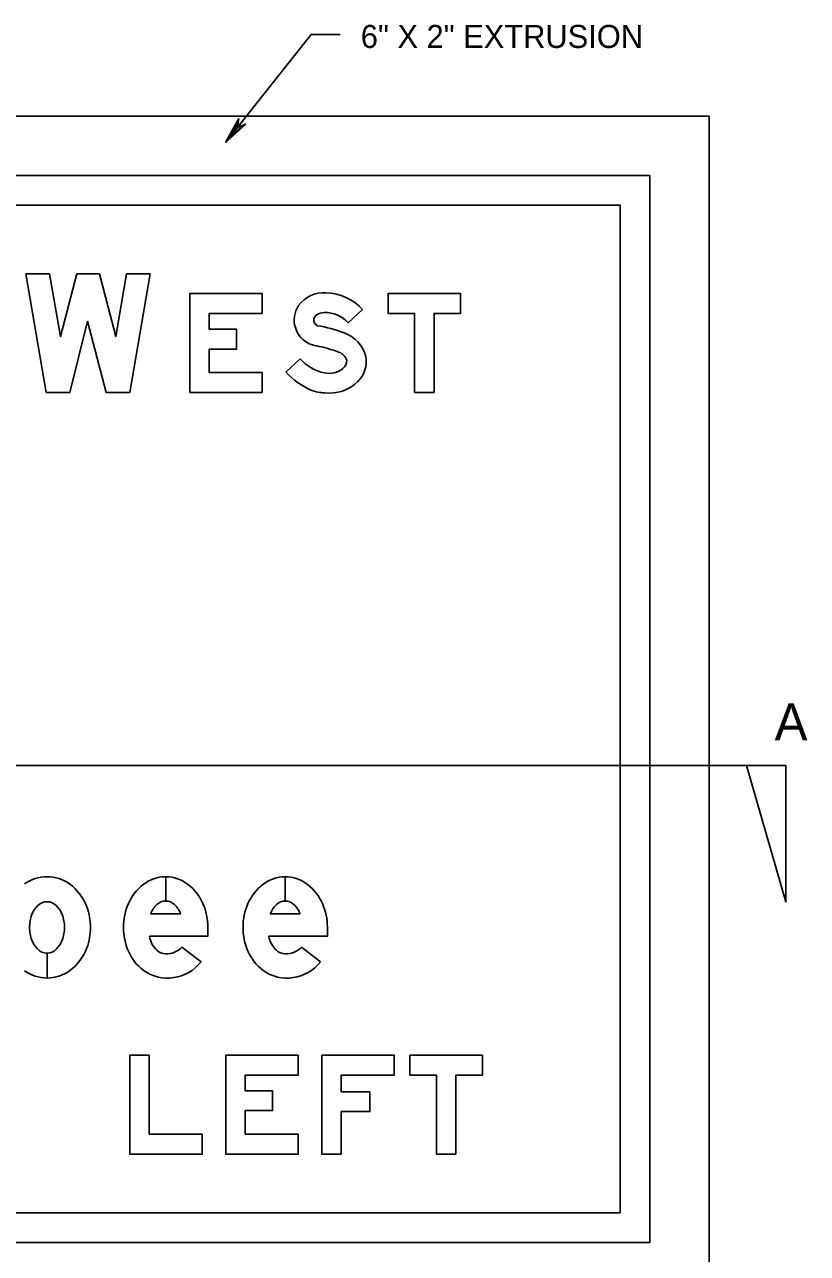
# Model space of a CAD drawing. Extents: x -897 to -114, y -697 to -235.
# Drawn here: x -281.9 to -163, y -536.1 to -349.4 of the extents above; entities that cross this region are included whole.
import ezdxf

# ---------------------------------------------------------------- set-up
doc = ezdxf.new("R2010")
doc.units = 0
for name, color, linetype in [('52', 7, 'Continuous'), ('SignPanel', 7, 'Continuous'), ('TextLabel', 7, 'Continuous')]:
    doc.layers.add(name, color=color, linetype=linetype)

msp = doc.modelspace()

# ---------------------------------------------------------------- linework, layer by layer
at = {"layer": '52'}
msp.add_lwpolyline([(-401.43, -482.68), (-401.43, -461.97), (-166.27, -461.97), (-166.27, -482.68)], dxfattribs=at)
msp.add_lwpolyline([(-166.27, -461.97), (-172.27, -461.97), (-166.27, -482.68)], close=True, dxfattribs=at)
at = {"layer": 'SignPanel'}
for p, q in [((-232.75, -394.74), (-230.57, -392.71)), ((-232.75, -394.74), (-230.57, -392.71)), ((-232.75, -394.74), (-230.57, -392.71)), ((-240.03, -400.18), (-242.22, -402.2)), ((-240.03, -400.18), (-242.22, -402.2)), ((-240.03, -400.18), (-242.22, -402.2)), ((-260.45, -478.84), (-260.45, -482.54)), ((-260.45, -482.54), (-260.45, -478.84)), ((-260.45, -478.84), (-260.45, -482.54)), ((-260.45, -482.54), (-260.45, -478.84)), ((-242.3, -478.84), (-242.3, -482.54)), ((-242.3, -482.54), (-242.3, -478.84)), ((-242.3, -478.84), (-242.3, -482.54)), ((-242.3, -482.54), (-242.3, -478.84)), ((-262.73, -484.47), (-258.17, -484.47)), ((-262.73, -484.47), (-258.17, -484.47)), ((-262.73, -484.47), (-258.17, -484.47)), ((-244.58, -484.47), (-240.02, -484.47)), ((-244.58, -484.47), (-240.02, -484.47)), ((-244.58, -484.47), (-240.02, -484.47)), ((-278.46, -490.44), (-278.46, -494.24)), ((-278.46, -494.24), (-278.46, -490.44)), ((-278.46, -490.44), (-278.46, -494.24)), ((-278.46, -494.24), (-278.46, -490.44)), ((-257.99, -489.52), (-255.08, -491.76)), ((-257.99, -489.52), (-255.08, -491.76)), ((-257.99, -489.52), (-255.08, -491.76)), ((-239.84, -489.52), (-236.93, -491.76)), ((-239.84, -489.52), (-236.93, -491.76)), ((-239.84, -489.52), (-236.93, -491.76))]:
    msp.add_line(p, q, dxfattribs=at)
for points in [[(-384.93, -543.37), (-177.93, -543.37), (-177.93, -363.37), (-384.93, -363.37)], [(-375.93, -534.37), (-186.93, -534.37), (-186.93, -372.37), (-375.93, -372.37)], [(-375.93, -534.37), (-186.93, -534.37), (-186.93, -372.37), (-375.93, -372.37)], [(-371.43, -529.87), (-191.43, -529.87), (-191.43, -376.87), (-371.43, -376.87)], [(-371.43, -529.87), (-371.43, -376.87), (-191.43, -376.87), (-191.43, -529.87)], [(-278.58, -405.3), (-281.67, -387.3), (-278.07, -387.3), (-276.43, -396.83), (-273.94, -387.3), (-270.51, -387.3), (-268.02, -396.83), (-266.38, -387.3), (-262.78, -387.3), (-265.87, -405.3), (-269.47, -405.3), (-272.3, -394.5), (-274.98, -405.3)], [(-278.58, -405.3), (-281.67, -387.3), (-278.07, -387.3), (-276.43, -396.83), (-273.94, -387.3), (-270.51, -387.3), (-268.02, -396.83), (-266.38, -387.3), (-262.78, -387.3), (-265.87, -405.3), (-269.47, -405.3), (-272.3, -394.5), (-274.98, -405.3)], [(-278.58, -405.3), (-281.67, -387.3), (-278.07, -387.3), (-276.43, -396.83), (-273.94, -387.3), (-270.51, -387.3), (-268.02, -396.83), (-266.38, -387.3), (-262.78, -387.3), (-265.87, -405.3), (-269.47, -405.3), (-272.3, -394.5), (-274.98, -405.3)], [(-245.78, -390.3), (-245.78, -393.3), (-253.83, -393.3), (-253.83, -395.71), (-249.68, -395.71), (-249.68, -398.71), (-253.83, -398.71), (-253.83, -402.3), (-245.78, -402.3), (-245.78, -405.3), (-256.78, -405.3), (-256.78, -390.3)], [(-245.78, -390.3), (-245.78, -393.3), (-253.83, -393.3), (-253.83, -395.71), (-249.68, -395.71), (-249.68, -398.71), (-253.83, -398.71), (-253.83, -402.3), (-245.78, -402.3), (-245.78, -405.3), (-256.78, -405.3), (-256.78, -390.3)], [(-245.78, -390.3), (-245.78, -393.3), (-253.83, -393.3), (-253.83, -395.71), (-249.68, -395.71), (-249.68, -398.71), (-253.83, -398.71), (-253.83, -402.3), (-245.78, -402.3), (-245.78, -405.3), (-256.78, -405.3), (-256.78, -390.3)], [(-219.69, -405.3), (-222.65, -405.3), (-222.65, -393.3), (-226.67, -393.3), (-226.67, -390.3), (-215.67, -390.3), (-215.67, -393.3), (-219.69, -393.3)], [(-219.69, -405.3), (-222.65, -405.3), (-222.65, -393.3), (-226.67, -393.3), (-226.67, -390.3), (-215.67, -390.3), (-215.67, -393.3), (-219.69, -393.3)], [(-219.69, -405.3), (-222.65, -405.3), (-222.65, -393.3), (-226.67, -393.3), (-226.67, -390.3), (-215.67, -390.3), (-215.67, -393.3), (-219.69, -393.3)], [(-262.94, -517.96), (-254.89, -517.96), (-254.89, -520.96), (-265.9, -520.96), (-265.9, -505.96), (-262.94, -505.96)], [(-262.94, -517.96), (-254.89, -517.96), (-254.89, -520.96), (-265.9, -520.96), (-265.9, -505.96), (-262.94, -505.96)], [(-262.94, -517.96), (-254.89, -517.96), (-254.89, -520.96), (-265.9, -520.96), (-265.9, -505.96), (-262.94, -505.96)], [(-240.31, -505.96), (-240.31, -508.96), (-248.36, -508.96), (-248.36, -511.37), (-244.22, -511.37), (-244.22, -514.37), (-248.36, -514.37), (-248.36, -517.96), (-240.31, -517.96), (-240.31, -520.96), (-251.32, -520.96), (-251.32, -505.96)], [(-240.31, -505.96), (-240.31, -508.96), (-248.36, -508.96), (-248.36, -511.37), (-244.22, -511.37), (-244.22, -514.37), (-248.36, -514.37), (-248.36, -517.96), (-240.31, -517.96), (-240.31, -520.96), (-251.32, -520.96), (-251.32, -505.96)], [(-240.31, -505.96), (-240.31, -508.96), (-248.36, -508.96), (-248.36, -511.37), (-244.22, -511.37), (-244.22, -514.37), (-248.36, -514.37), (-248.36, -517.96), (-240.31, -517.96), (-240.31, -520.96), (-251.32, -520.96), (-251.32, -505.96)], [(-236.74, -505.96), (-225.74, -505.96), (-225.74, -508.96), (-233.79, -508.96), (-233.79, -511.52), (-229.43, -511.52), (-229.43, -514.52), (-233.79, -514.52), (-233.79, -520.96), (-236.74, -520.96)], [(-236.74, -505.96), (-225.74, -505.96), (-225.74, -508.96), (-233.79, -508.96), (-233.79, -511.52), (-229.43, -511.52), (-229.43, -514.52), (-233.79, -514.52), (-233.79, -520.96), (-236.74, -520.96)], [(-236.74, -505.96), (-225.74, -505.96), (-225.74, -508.96), (-233.79, -508.96), (-233.79, -511.52), (-229.43, -511.52), (-229.43, -514.52), (-233.79, -514.52), (-233.79, -520.96), (-236.74, -520.96)], [(-216.38, -520.96), (-219.33, -520.96), (-219.33, -508.96), (-223.36, -508.96), (-223.36, -505.96), (-212.35, -505.96), (-212.35, -508.96), (-216.38, -508.96)], [(-216.38, -520.96), (-219.33, -520.96), (-219.33, -508.96), (-223.36, -508.96), (-223.36, -505.96), (-212.35, -505.96), (-212.35, -508.96), (-216.38, -508.96)], [(-216.38, -520.96), (-219.33, -520.96), (-219.33, -508.96), (-223.36, -508.96), (-223.36, -505.96), (-212.35, -505.96), (-212.35, -508.96), (-216.38, -508.96)]]:
    msp.add_lwpolyline(points, close=True, dxfattribs=at)
for points in [[(-254.05, -486.54), (-254.05, -487.88), (-262.93, -487.88)], [(-254.05, -486.54), (-254.05, -487.88), (-262.93, -487.88)], [(-254.05, -486.54), (-254.05, -487.88), (-262.93, -487.88)], [(-235.9, -486.54), (-235.9, -487.88), (-244.78, -487.88)], [(-235.9, -486.54), (-235.9, -487.88), (-244.78, -487.88)], [(-235.9, -486.54), (-235.9, -487.88), (-244.78, -487.88)]]:
    msp.add_lwpolyline(points, dxfattribs=at)
for centre, major_axis, start_param, end_param in [((-236.38, -395.12), (0, 4.97), 6.22585, 7.204805), ((-236.38, -395.12), (0, 4.97), 6.22585, 7.204805), ((-236.38, -395.12), (0, 4.97), 6.22585, 7.204805), ((-236.32, -398.11), (0, 7.96), 5.45828, 6.253918), ((-236.32, -398.11), (0, 7.96), 5.45828, 6.253918), ((-236.32, -398.11), (0, 7.96), 5.45828, 6.253918), ((-237.07, -394.31), (0, 3.92), 0.976932, 2.761526), ((-237.07, -394.31), (0, 3.92), 0.976932, 2.761526), ((-237.07, -394.31), (0, 3.92), 0.976932, 2.761526), ((-237.09, -394.32), (0, 0.896), 0.489453, 2.797937), ((-237.09, -394.32), (0, 0.896), 0.489453, 2.797937), ((-237.09, -394.32), (0, 0.896), 0.489453, 2.797937), ((-236.27, -395.53), (0, 2.36), 0.051099, 0.560381), ((-236.27, -395.53), (0, 2.36), 0.051099, 0.560381), ((-236.27, -395.53), (0, 2.36), 0.051099, 0.560381), ((-236.15, -397.75), (0, 4.58), 5.429459, 6.3353), ((-236.15, -397.75), (0, 4.58), 5.429459, 6.3353), ((-236.15, -397.75), (0, 4.58), 5.429459, 6.3353), ((-241.01, -417.14), (0, 22.28), 5.927499, 6.117503), ((-241.01, -417.14), (0, 22.28), 5.927499, 6.117503), ((-241.01, -417.14), (0, 22.28), 5.927499, 6.117503), ((-234.96, -401.16), (0, 5.16), 4.967514, 5.964052), ((-234.96, -401.16), (0, 5.16), 4.967514, 5.964052), ((-234.96, -401.16), (0, 5.16), 4.967514, 5.964052), ((-235.56, -389.29), (0, 9.16), 2.808858, 2.963856), ((-235.56, -389.29), (0, 9.16), 2.808858, 2.963856), ((-235.56, -389.29), (0, 9.16), 2.808858, 2.963856), ((-242.79, -424.08), (0, 26.4), 5.940509, 6.064763), ((-242.79, -424.08), (0, 26.4), 5.940509, 6.064763), ((-242.79, -424.08), (0, 26.4), 5.940509, 6.064763), ((-234.8, -401.03), (0, 1.97), 5.035719, 5.886297), ((-234.8, -401.03), (0, 1.97), 5.035719, 5.886297), ((-234.8, -401.03), (0, 1.97), 5.035719, 5.886297), ((-235.05, -395.76), (0, 6.71), 2.289515, 2.944644), ((-235.05, -395.76), (0, 6.71), 2.289515, 2.944644), ((-235.05, -395.76), (0, 6.71), 2.289515, 2.944644), ((-234.47, -400.48), (0, 1.53), 3.808537, 4.760948), ((-234.47, -400.48), (0, 1.53), 3.808537, 4.760948), ((-234.47, -400.48), (0, 1.53), 3.808537, 4.760948), ((-234.18, -400.57), (0, 4.26), 3.912503, 4.881073), ((-234.18, -400.57), (0, 4.26), 3.912503, 4.881073), ((-234.18, -400.57), (0, 4.26), 3.912503, 4.881073), ((-233.55, -393.9), (0, 12.09), 2.326579, 2.726842), ((-233.55, -393.9), (0, 12.09), 2.326579, 2.726842), ((-233.55, -393.9), (0, 12.09), 2.326579, 2.726842), ((-235.66, -398.84), (0, 3.57), 2.944399, 3.788539), ((-235.66, -398.84), (0, 3.57), 2.944399, 3.788539), ((-235.66, -398.84), (0, 3.57), 2.944399, 3.788539), ((-235.58, -399.14), (0, 6.28), 3.01776, 3.916355), ((-235.58, -399.14), (0, 6.28), 3.01776, 3.916355), ((-235.58, -399.14), (0, 6.28), 3.01776, 3.916355), ((-235.86, -397.44), (0, 7.95), 2.817761, 3.079327), ((-235.86, -397.44), (0, 7.95), 2.817761, 3.079327), ((-235.86, -397.44), (0, 7.95), 2.817761, 3.079327), ((-278.46, -484.82), (0, 5.98), 0, 0.617483), ((-278.46, -484.82), (0, 5.98), 0, 0.617483), ((-278.46, -484.82), (0, 5.98), 0, 0.617483), ((-278.46, -484.82), (0, 5.98), 5.665702, 6.283185), ((-278.46, -484.82), (0, 5.98), 5.665702, 6.283185), ((-278.46, -484.82), (0, 5.98), 5.665702, 6.283185), ((-260.45, -484.5), (0, 5.66), 0, 0.658026), ((-260.45, -484.5), (0, 5.66), 0, 0.658026), ((-260.45, -484.5), (0, 5.66), 0, 0.658026), ((-260.45, -484.5), (0, 5.66), 5.625159, 6.283185), ((-260.45, -484.5), (0, 5.66), 5.62516, 6.283009), ((-260.45, -484.5), (0, 5.66), 5.62516, 6.283009), ((-242.3, -484.5), (0, 5.66), 0, 0.658026), ((-242.3, -484.5), (0, 5.66), 0, 0.658026), ((-242.3, -484.5), (0, 5.66), 0, 0.658026), ((-242.3, -484.5), (0, 5.66), 5.625159, 6.283185), ((-242.3, -484.5), (0, 5.66), 5.62516, 6.283009), ((-242.3, -484.5), (0, 5.66), 5.62516, 6.283009), ((-279.37, -486.06), (0, 7.52), 5.067913, 5.660802), ((-279.37, -486.06), (0, 7.52), 5.067913, 5.660802), ((-279.37, -486.06), (0, 7.52), 5.067913, 5.660802), ((-259.46, -485.87), (0, 7.36), 0.651793, 1.157519), ((-259.46, -485.87), (0, 7.36), 0.651793, 1.157519), ((-259.46, -485.87), (0, 7.36), 0.651793, 1.157519), ((-261.44, -485.87), (0, 7.36), 5.125666, 5.631392), ((-261.44, -485.87), (0, 7.36), 5.125666, 5.631392), ((-261.44, -485.87), (0, 7.36), 5.125666, 5.631392), ((-241.31, -485.87), (0, 7.36), 0.651793, 1.157519), ((-241.31, -485.87), (0, 7.36), 0.651793, 1.157519), ((-241.31, -485.87), (0, 7.36), 0.651793, 1.157519), ((-243.29, -485.87), (0, 7.36), 5.125666, 5.631392), ((-243.29, -485.87), (0, 7.36), 5.125666, 5.631392), ((-243.29, -485.87), (0, 7.36), 5.125666, 5.631392), ((-277.3, -485.96), (0, 3.77), 0.7749, 1.203152), ((-277.3, -485.96), (0, 3.77), 0.7749, 1.203152), ((-277.3, -485.96), (0, 3.77), 0.7749, 1.203152), ((-278.46, -484.67), (0, 2.03), 0, 0.804581), ((-278.46, -484.67), (0, 2.03), 0, 0.804581), ((-278.46, -484.67), (0, 2.03), 0, 0.804581), ((-278.46, -484.67), (0, 2.03), 5.478604, 6.283185), ((-278.46, -484.67), (0, 2.03), 5.478604, 6.283185), ((-278.46, -484.67), (0, 2.03), 5.478604, 6.283185), ((-279.62, -485.96), (0, 3.77), 5.080033, 5.508286), ((-279.62, -485.96), (0, 3.77), 5.080033, 5.508286), ((-279.62, -485.96), (0, 3.77), 5.080033, 5.508286), ((-258.02, -486.54), (0, 8.97), 1.154884, 1.570796), ((-258.02, -486.54), (0, 8.97), 1.154884, 1.570796), ((-258.02, -486.54), (0, 8.97), 1.154884, 1.570796), ((-259.31, -485.84), (0, 3.73), 0.73953, 1.195663), ((-259.31, -485.84), (0, 3.73), 0.73953, 1.195663), ((-259.31, -485.84), (0, 3.73), 0.73953, 1.195663), ((-260.45, -484.51), (0, 1.97), 0, 0.759075), ((-260.45, -484.51), (0, 1.97), 0, 0.759075), ((-260.45, -484.51), (0, 1.97), 0, 0.759075), ((-260.45, -484.51), (0, 1.97), 5.52411, 6.283185), ((-260.45, -484.51), (0, 1.97), 5.52411, 6.282678), ((-260.45, -484.51), (0, 1.97), 5.52411, 6.282678), ((-261.6, -485.84), (0, 3.73), 5.087522, 5.543655), ((-261.6, -485.84), (0, 3.73), 5.087522, 5.543655), ((-261.6, -485.84), (0, 3.73), 5.087522, 5.543655), ((-262.88, -486.54), (0, 8.97), 4.712389, 5.128302), ((-262.88, -486.54), (0, 8.97), 4.712389, 5.128302), ((-262.88, -486.54), (0, 8.97), 4.712389, 5.128302), ((-239.87, -486.54), (0, 8.97), 1.154884, 1.570796), ((-239.87, -486.54), (0, 8.97), 1.154884, 1.570796), ((-239.87, -486.54), (0, 8.97), 1.154884, 1.570796), ((-241.16, -485.84), (0, 3.73), 0.73953, 1.195663), ((-241.16, -485.84), (0, 3.73), 0.73953, 1.195663), ((-241.16, -485.84), (0, 3.73), 0.73953, 1.195663), ((-242.3, -484.51), (0, 1.97), 0, 0.759075), ((-242.3, -484.51), (0, 1.97), 0, 0.759075), ((-242.3, -484.51), (0, 1.97), 0, 0.759075), ((-242.3, -484.51), (0, 1.97), 5.52411, 6.283185), ((-242.3, -484.51), (0, 1.97), 5.52411, 6.282678), ((-242.3, -484.51), (0, 1.97), 5.52411, 6.282678), ((-243.44, -485.84), (0, 3.73), 5.087522, 5.543655), ((-243.44, -485.84), (0, 3.73), 5.087522, 5.543655), ((-243.44, -485.84), (0, 3.73), 5.087522, 5.543655), ((-244.73, -486.54), (0, 8.97), 4.712389, 5.128302), ((-244.73, -486.54), (0, 8.97), 4.712389, 5.128302), ((-244.73, -486.54), (0, 8.97), 4.712389, 5.128302), ((-275.74, -486.54), (0, 5.46), 1.208569, 1.570796), ((-275.74, -486.54), (0, 5.46), 1.208569, 1.570796), ((-275.74, -486.54), (0, 5.46), 1.208569, 1.570796), ((-281.19, -486.54), (0, 5.46), 4.712389, 5.074617), ((-281.19, -486.54), (0, 5.46), 4.712389, 5.074617), ((-281.19, -486.54), (0, 5.46), 4.712389, 5.074617), ((-280.49, -486.54), (0, 8.76), 4.712389, 5.074107), ((-280.49, -486.54), (0, 8.76), 4.712389, 5.074107), ((-280.49, -486.54), (0, 8.76), 4.712389, 5.074107), ((-275.74, -486.54), (0, 5.46), 1.570796, 1.933024), ((-275.74, -486.54), (0, 5.46), 1.570796, 1.933024), ((-275.74, -486.54), (0, 5.46), 1.570796, 1.933024), ((-281.19, -486.54), (0, 5.46), 4.350161, 4.712389), ((-281.19, -486.54), (0, 5.46), 4.350161, 4.712389), ((-281.19, -486.54), (0, 5.46), 4.350161, 4.712389), ((-280.49, -486.54), (0, 8.76), 4.350671, 4.712389), ((-280.49, -486.54), (0, 8.76), 4.350671, 4.712389), ((-280.49, -486.54), (0, 8.76), 4.350671, 4.712389), ((-258.02, -486.54), (0, 8.97), 1.570796, 1.986709), ((-258.02, -486.54), (0, 8.97), 1.570796, 1.986709), ((-258.02, -486.54), (0, 8.97), 1.570796, 1.986709), ((-239.87, -486.54), (0, 8.97), 1.570796, 1.986709), ((-239.87, -486.54), (0, 8.97), 1.570796, 1.986709), ((-239.87, -486.54), (0, 8.97), 1.570796, 1.986709), ((-277.3, -487.12), (0, 3.77), 1.93844, 2.366693), ((-277.3, -487.12), (0, 3.77), 1.93844, 2.366693), ((-277.3, -487.12), (0, 3.77), 1.93844, 2.366693), ((-279.62, -487.12), (0, 3.77), 3.916492, 4.344745), ((-279.62, -487.12), (0, 3.77), 3.916492, 4.344745), ((-279.62, -487.12), (0, 3.77), 3.916492, 4.344745), ((-259.31, -487.24), (0, 3.73), 1.743279, 2.402063), ((-259.31, -487.24), (0, 3.73), 1.743279, 2.402063), ((-259.31, -487.24), (0, 3.73), 1.743279, 2.402063), ((-241.16, -487.24), (0, 3.73), 1.743279, 2.402063), ((-241.16, -487.24), (0, 3.73), 1.743279, 2.402063), ((-241.16, -487.24), (0, 3.73), 1.743279, 2.402063), ((-278.46, -488.41), (0, 2.03), 2.337012, 3.141593), ((-278.46, -488.41), (0, 2.03), 2.337012, 3.1411), ((-278.46, -488.41), (0, 2.03), 2.337012, 3.1411), ((-278.46, -488.41), (0, 2.03), 3.141593, 3.946173), ((-278.46, -488.41), (0, 2.03), 3.141593, 3.946173), ((-278.46, -488.41), (0, 2.03), 3.141593, 3.946173), ((-279.37, -487.02), (0, 7.52), 3.763976, 4.356865), ((-279.37, -487.02), (0, 7.52), 3.763976, 4.356865), ((-279.37, -487.02), (0, 7.52), 3.763976, 4.356865), ((-259.46, -487.2), (0, 7.36), 1.984073, 2.489799), ((-259.46, -487.2), (0, 7.36), 1.984073, 2.489799), ((-259.46, -487.2), (0, 7.36), 1.984073, 2.489799), ((-260.45, -488.57), (0, 1.97), 2.382517, 3.141593), ((-260.45, -488.57), (0, 1.97), 2.382517, 3.141593), ((-260.45, -488.57), (0, 1.97), 2.382517, 3.141593), ((-260.29, -487.36), (0, 3.19), 3.089457, 3.963679), ((-260.29, -487.36), (0, 3.19), 3.089457, 3.963679), ((-260.29, -487.36), (0, 3.19), 3.089457, 3.963679), ((-241.31, -487.2), (0, 7.36), 1.984073, 2.489799), ((-241.31, -487.2), (0, 7.36), 1.984073, 2.489799), ((-241.31, -487.2), (0, 7.36), 1.984073, 2.489799), ((-242.3, -488.57), (0, 1.97), 2.382517, 3.141593), ((-242.3, -488.57), (0, 1.97), 2.382517, 3.141593), ((-242.3, -488.57), (0, 1.97), 2.382517, 3.141593), ((-242.14, -487.36), (0, 3.19), 3.089457, 3.963679), ((-242.14, -487.36), (0, 3.19), 3.089457, 3.963679), ((-242.14, -487.36), (0, 3.19), 3.089457, 3.963679), ((-260.15, -487.65), (0, 6.59), 2.533552, 4.037888), ((-260.15, -487.65), (0, 6.59), 2.533552, 4.037888), ((-260.15, -487.65), (0, 6.59), 2.533552, 4.037888), ((-242, -487.65), (0, 6.59), 2.533552, 4.037888), ((-242, -487.65), (0, 6.59), 2.533552, 4.037888), ((-242, -487.65), (0, 6.59), 2.533552, 4.037888), ((-278.46, -488.25), (0, 5.98), 2.524109, 3.141593), ((-278.46, -488.25), (0, 5.98), 2.524109, 3.141426), ((-278.46, -488.25), (0, 5.98), 2.524109, 3.141426), ((-278.46, -488.25), (0, 5.98), 3.141593, 3.759076), ((-278.46, -488.25), (0, 5.98), 3.141593, 3.759076), ((-278.46, -488.25), (0, 5.98), 3.141593, 3.759076)]:
    msp.add_ellipse(centre, major_axis=major_axis, ratio=0.985, start_param=start_param, end_param=end_param, dxfattribs=at)
at = {"layer": 'TextLabel'}
for p, q in [((-251.38, -367.37), (-249.36, -363.71)), ((-249.36, -363.71), (-249.54, -365.04)), ((-249.45, -364.38), (-251.38, -367.37)), ((-248.29, -364.58), (-251.38, -367.37)), ((-248.91, -364.81), (-251.38, -367.37)), ((-249.54, -365.04), (-248.29, -364.58))]:
    msp.add_line(p, q, dxfattribs=at)
msp.add_lwpolyline([(-233.93, -350.95), (-238.36, -350.95), (-251.38, -367.37)], dxfattribs=at)

# ---------------------------------------------------------------- texts
at = {"layer": '52'}
msp.add_text('A', height=5.6, dxfattribs=at).set_placement((-167.98, -458.14))
at = {"layer": 'TextLabel'}
msp.add_text('6" X 2" EXTRUSION', height=3.5, dxfattribs=at).set_placement((-230.82, -352.99))

doc.saveas('drawing.dxf')
